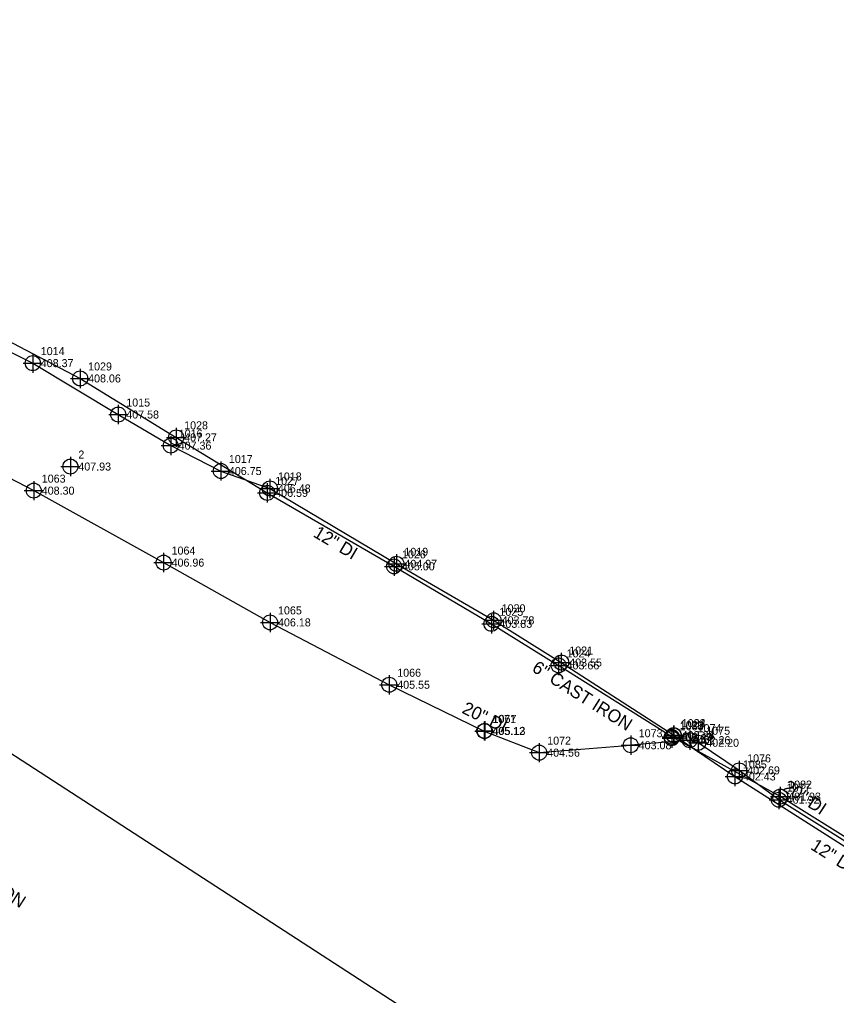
# Model space of a CAD drawing. Extents: x 2024146 to 2025516, y 819906 to 820765.
# Drawn here: x 2024389.9 to 2024645.2, y 820438.4 to 820743.2 of the extents above; entities that cross this region are included whole.
import ezdxf

# ---------------------------------------------------------------- set-up
doc = ezdxf.new("R2010")
doc.units = 0
for name, color, linetype in [('Prop Conc 4in Sidewalk', 7, 'Continuous'), ('Prop DSN Text', 7, 'Continuous'), ('Prop Lane Lines', 7, 'Continuous'), ('Sheet Block Revision CELL', 7, 'Continuous'), ('Sheet Data Field CELL', 7, 'Continuous'), ('Sheet Layout Plan Border', 7, 'Continuous'), ('Sheet Layout Profile Border Port 2', 7, 'Continuous'), ('Sheet Plan And Profile CELL', 7, 'Continuous'), ('Sheet Profile Grid Minor CELL', 7, 'Continuous')]:
    doc.layers.add(name, color=color, linetype=linetype)

msp = doc.modelspace()

# ---------------------------------------------------------------- linework, layer by layer
at = {"layer": 'Prop Lane Lines'}
msp.add_lwpolyline([(2024146.4, 820670.11), (2024566.33, 820397.9)], dxfattribs=at)
at = {"layer": 'Sheet Layout Plan Border'}
for points in [[(2024394.04, 820638.87), (2024394.04, 820635.87)], [(2024391.04, 820635.87), (2024394.04, 820635.87)], [(2024394.04, 820635.87), (2024397.04, 820635.87)], [(2024394.04, 820635.87), (2024394.04, 820632.87)], [(2024408.84, 820634.09), (2024408.84, 820631.09)], [(2024405.84, 820631.09), (2024408.84, 820631.09)], [(2024408.84, 820631.09), (2024411.84, 820631.09)], [(2024408.84, 820631.09), (2024408.84, 820628.09)], [(2024420.76, 820622.82), (2024420.76, 820619.82)], [(2024417.76, 820619.82), (2024420.76, 820619.82)], [(2024420.76, 820619.82), (2024423.76, 820619.82)], [(2024420.76, 820619.82), (2024420.76, 820616.82)], [(2024438.85, 820615.69), (2024438.85, 820612.69)], [(2024435.85, 820612.69), (2024438.85, 820612.69)], [(2024437.15, 820613.11), (2024437.15, 820610.11)], [(2024438.85, 820612.69), (2024441.85, 820612.69)], [(2024438.85, 820612.69), (2024438.85, 820609.69)], [(2024434.15, 820610.11), (2024437.15, 820610.11)], [(2024437.15, 820610.11), (2024440.15, 820610.11)], [(2024437.15, 820610.11), (2024437.15, 820607.11)], [(2024405.78, 820606.57), (2024405.78, 820603.57)], [(2024402.78, 820603.57), (2024405.78, 820603.57)], [(2024405.78, 820603.57), (2024408.78, 820603.57)], [(2024405.78, 820603.57), (2024405.78, 820600.57)], [(2024452.82, 820605.18), (2024452.82, 820602.18)], [(2024449.82, 820602.18), (2024452.82, 820602.18)], [(2024452.82, 820602.18), (2024455.82, 820602.18)], [(2024452.82, 820602.18), (2024452.82, 820599.18)], [(2024468.14, 820599.72), (2024468.14, 820596.72)], [(2024394.35, 820599.05), (2024394.35, 820596.05)], [(2024465.14, 820596.72), (2024468.14, 820596.72)], [(2024467.31, 820598.35), (2024467.31, 820595.35)], [(2024468.14, 820596.72), (2024471.14, 820596.72)], [(2024468.14, 820596.72), (2024468.14, 820593.72)], [(2024391.35, 820596.05), (2024394.35, 820596.05)], [(2024394.35, 820596.05), (2024397.35, 820596.05)], [(2024394.35, 820596.05), (2024394.35, 820593.05)], [(2024464.31, 820595.35), (2024467.31, 820595.35)], [(2024467.31, 820595.35), (2024470.31, 820595.35)], [(2024467.31, 820595.35), (2024467.31, 820592.35)], [(2024434.92, 820576.57), (2024434.92, 820573.57)], [(2024506.93, 820575.4), (2024506.93, 820572.4)], [(2024507.67, 820576.2), (2024507.67, 820573.2)], [(2024431.92, 820573.57), (2024434.92, 820573.57)], [(2024434.92, 820573.57), (2024437.92, 820573.57)], [(2024434.92, 820573.57), (2024434.92, 820570.57)], [(2024503.93, 820572.4), (2024506.93, 820572.4)], [(2024504.67, 820573.2), (2024507.67, 820573.2)], [(2024506.93, 820572.4), (2024509.93, 820572.4)], [(2024506.93, 820572.4), (2024506.93, 820569.4)], [(2024507.67, 820573.2), (2024510.67, 820573.2)], [(2024507.67, 820573.2), (2024507.67, 820570.2)], [(2024468.18, 820557.89), (2024468.18, 820554.89)], [(2024537.38, 820557.46), (2024537.38, 820554.46)], [(2024538.07, 820558.55), (2024538.07, 820555.55)], [(2024465.18, 820554.89), (2024468.18, 820554.89)], [(2024468.18, 820554.89), (2024471.18, 820554.89)], [(2024468.18, 820554.89), (2024468.18, 820551.89)], [(2024534.38, 820554.46), (2024537.38, 820554.46)], [(2024535.07, 820555.55), (2024538.07, 820555.55)], [(2024537.38, 820554.46), (2024540.38, 820554.46)], [(2024537.38, 820554.46), (2024537.38, 820551.46)], [(2024538.07, 820555.55), (2024541.07, 820555.55)], [(2024538.07, 820555.55), (2024538.07, 820552.55)], [(2024559.19, 820545.36), (2024559.19, 820542.36)], [(2024556.19, 820542.36), (2024559.19, 820542.36)], [(2024558.37, 820544.46), (2024558.37, 820541.46)], [(2024559.19, 820542.36), (2024562.19, 820542.36)], [(2024559.19, 820542.36), (2024559.19, 820539.36)], [(2024555.37, 820541.46), (2024558.37, 820541.46)], [(2024558.37, 820541.46), (2024561.37, 820541.46)], [(2024558.37, 820541.46), (2024558.37, 820538.46)], [(2024505.44, 820538.42), (2024505.44, 820535.42)], [(2024502.44, 820535.42), (2024505.44, 820535.42)], [(2024505.44, 820535.42), (2024508.44, 820535.42)], [(2024505.44, 820535.42), (2024505.44, 820532.42)], [(2024535.14, 820523.96), (2024535.14, 820520.96)], [(2024535.27, 820524.01), (2024535.27, 820521.01)], [(2024532.14, 820520.96), (2024535.14, 820520.96)], [(2024532.27, 820521.01), (2024535.27, 820521.01)], [(2024535.14, 820520.96), (2024538.14, 820520.96)], [(2024535.14, 820520.96), (2024535.14, 820517.96)], [(2024535.27, 820521.01), (2024538.27, 820521.01)], [(2024535.27, 820521.01), (2024535.27, 820518.01)], [(2024593.71, 820521.72), (2024593.71, 820518.72)], [(2024593.76, 820522.11), (2024593.76, 820519.11)], [(2024594.32, 820522.65), (2024594.32, 820519.65)], [(2024594.35, 820522.69), (2024594.35, 820519.69)], [(2024599.33, 820521.11), (2024599.33, 820518.11)], [(2024602.02, 820520.3), (2024602.02, 820517.3)], [(2024580.9, 820519.52), (2024580.9, 820516.52)], [(2024590.71, 820518.72), (2024593.71, 820518.72)], [(2024590.76, 820519.11), (2024593.76, 820519.11)], [(2024591.32, 820519.65), (2024594.32, 820519.65)], [(2024591.35, 820519.69), (2024594.35, 820519.69)], [(2024593.71, 820518.72), (2024596.71, 820518.72)], [(2024593.71, 820518.72), (2024593.71, 820515.72)], [(2024593.76, 820519.11), (2024596.76, 820519.11)], [(2024593.76, 820519.11), (2024593.76, 820516.11)], [(2024594.32, 820519.65), (2024597.32, 820519.65)], [(2024594.32, 820519.65), (2024594.32, 820516.65)], [(2024594.35, 820519.69), (2024597.35, 820519.69)], [(2024594.35, 820519.69), (2024594.35, 820516.69)], [(2024596.33, 820518.11), (2024599.33, 820518.11)], [(2024599.02, 820517.3), (2024602.02, 820517.3)], [(2024599.33, 820518.11), (2024602.33, 820518.11)], [(2024599.33, 820518.11), (2024599.33, 820515.11)], [(2024602.02, 820517.3), (2024605.02, 820517.3)], [(2024602.02, 820517.3), (2024602.02, 820514.3)], [(2024549.3, 820514.21), (2024552.3, 820514.21)], [(2024552.3, 820517.21), (2024552.3, 820514.21)], [(2024552.3, 820514.21), (2024555.3, 820514.21)], [(2024552.3, 820514.21), (2024552.3, 820511.21)], [(2024577.9, 820516.52), (2024580.9, 820516.52)], [(2024580.9, 820516.52), (2024583.9, 820516.52)], [(2024580.9, 820516.52), (2024580.9, 820513.52)], [(2024614.79, 820511.68), (2024614.79, 820508.68)], [(2024611.79, 820508.68), (2024614.79, 820508.68)], [(2024613.47, 820509.78), (2024613.47, 820506.78)], [(2024614.79, 820508.68), (2024617.79, 820508.68)], [(2024614.79, 820508.68), (2024614.79, 820505.68)], [(2024610.47, 820506.78), (2024613.47, 820506.78)], [(2024613.47, 820506.78), (2024616.47, 820506.78)], [(2024613.47, 820506.78), (2024613.47, 820503.78)], [(2024627.17, 820502.52), (2024627.17, 820499.52)], [(2024627.61, 820503.49), (2024627.61, 820500.49)], [(2024624.17, 820499.52), (2024627.17, 820499.52)], [(2024624.61, 820500.49), (2024627.61, 820500.49)], [(2024627.17, 820499.52), (2024630.17, 820499.52)], [(2024627.17, 820499.52), (2024627.17, 820496.52)], [(2024627.61, 820500.49), (2024630.61, 820500.49)], [(2024627.61, 820500.49), (2024627.61, 820497.49)]]:
    msp.add_lwpolyline(points, dxfattribs=at)
for centre in [(2024394.04, 820635.87), (2024408.84, 820631.09), (2024420.76, 820619.82), (2024438.85, 820612.69), (2024437.15, 820610.11), (2024405.78, 820603.57), (2024452.82, 820602.18), (2024394.35, 820596.05), (2024467.31, 820595.35), (2024468.14, 820596.72), (2024434.92, 820573.57), (2024507.67, 820573.2), (2024506.93, 820572.4), (2024468.18, 820554.89), (2024538.07, 820555.55), (2024537.38, 820554.46), (2024559.19, 820542.36), (2024558.37, 820541.46), (2024505.44, 820535.42), (2024535.27, 820521.01), (2024535.14, 820520.96), (2024593.71, 820518.72), (2024593.76, 820519.11), (2024594.32, 820519.65), (2024594.35, 820519.69), (2024599.33, 820518.11), (2024580.9, 820516.52), (2024602.02, 820517.3), (2024552.3, 820514.21), (2024613.47, 820506.78), (2024614.79, 820508.68), (2024627.61, 820500.49), (2024627.17, 820499.52)]:
    msp.add_circle(centre, 2.34, dxfattribs=at)
at = {"layer": 'Sheet Plan And Profile CELL'}
for points in [[(2024210.98, 820743.19), (2024217.84, 820738.78), (2024244.24, 820722.31), (2024274.15, 820703.11), (2024311.17, 820681.15), (2024338.73, 820664.66), (2024357.44, 820654.15), (2024394.04, 820635.87), (2024420.76, 820619.83), (2024437.14, 820610.11), (2024452.82, 820602.18), (2024468.13, 820596.73), (2024507.66, 820573.2), (2024538.06, 820555.55), (2024559.18, 820542.37)], [(2024191.85, 820713.95), (2024208.67, 820704.14), (2024239.83, 820686.43), (2024256.4, 820676.24), (2024257.02, 820675.83), (2024287.67, 820658.15), (2024296.47, 820653.07), (2024329.77, 820633.23), (2024370.42, 820608.44), (2024394.34, 820596.06), (2024434.92, 820573.58), (2024468.18, 820554.9), (2024505.43, 820535.43), (2024535.14, 820520.96), (2024552.3, 820514.21)], [(2024559.18, 820542.37), (2024594.35, 820519.69), (2024613.47, 820506.78), (2024651.26, 820482.68)], [(2024698.94, 820453.07), (2024674.33, 820469.18), (2024651.95, 820483.99), (2024627.17, 820499.52), (2024614.79, 820508.68), (2024602.02, 820517.3), (2024599.33, 820518.11), (2024580.9, 820516.52)], [(2024552.3, 820514.21), (2024580.9, 820516.52), (2024581.27, 820516.52)]]:
    msp.add_lwpolyline(points, dxfattribs=at)
at = {"layer": 'Sheet Profile Grid Minor CELL'}
for points in [[(2024310.64, 820680.27), (2024313.64, 820678.67), (2024339.38, 820665.59), (2024349.09, 820660.35), (2024374.95, 820648.82), (2024408.83, 820631.1), (2024438.84, 820612.69), (2024467.31, 820595.36), (2024506.92, 820572.41), (2024537.38, 820554.46), (2024558.37, 820541.47)], [(2024627.61, 820500.49), (2024593.76, 820519.11), (2024558.37, 820541.47)], [(2024699.98, 820453.54), (2024675.04, 820469.96), (2024652.27, 820485.09), (2024627.61, 820500.49)]]:
    msp.add_lwpolyline(points, dxfattribs=at)

# ---------------------------------------------------------------- texts
at = {"layer": 'Prop Conc 4in Sidewalk'}
msp.add_text('6" CAST IRON', height=4, rotation=327.7187, dxfattribs=at).set_placement((2024549.76, 820539.81))
at = {"layer": 'Prop DSN Text'}
msp.add_text('24" PIPE NOT INCLUDED IN INVESTIGATION', height=4, rotation=327.0479, dxfattribs=at).set_placement((2024295.56, 820526.85))
at = {"layer": 'Sheet Block Revision CELL'}
for s, p in [('1014', (2024396.54, 820638.37)), ('1029', (2024411.34, 820633.59)), ('1015', (2024423.26, 820622.32)), ('1016', (2024439.65, 820612.61)), ('1028', (2024441.35, 820615.19)), ('2', (2024408.28, 820606.07)), ('1017', (2024455.32, 820604.68)), ('1063', (2024396.85, 820598.55)), ('1027', (2024469.81, 820597.85)), ('1018', (2024470.64, 820599.22)), ('1064', (2024437.42, 820576.07)), ('1019', (2024510.17, 820575.7)), ('1026', (2024509.43, 820574.9)), ('1065', (2024470.68, 820557.39)), ('1020', (2024540.57, 820558.05)), ('1025', (2024539.88, 820556.96)), ('1024', (2024560.87, 820543.96)), ('1021', (2024561.69, 820544.86)), ('1066', (2024507.94, 820537.92)), ('1071', (2024537.64, 820523.46)), ('1067', (2024537.77, 820523.51)), ('1083', (2024596.21, 820521.22)), ('1023', (2024596.26, 820521.61)), ('1022', (2024596.82, 820522.16)), ('1084', (2024596.85, 820522.19)), ('1073', (2024583.4, 820519.02)), ('1074', (2024601.83, 820520.61)), ('1075', (2024604.52, 820519.8)), ('1072', (2024554.8, 820516.71)), ('1085', (2024615.97, 820509.28)), ('1076', (2024617.29, 820511.18)), ('1082', (2024630.11, 820502.99)), ('1077', (2024629.67, 820502.02))]:
    msp.add_text(s, height=2.5, dxfattribs=at).set_placement(p)
at = {"layer": 'Sheet Data Field CELL'}
for s, rotation, p in [('12" DI', 329.2487, (2024481.39, 820581.85)), ('20" DI', 334.0336, (2024527.87, 820526.73)), ('20" DI', 326.8369, (2024628.09, 820502.61)), ('12" DI', 327.9136, (2024636.82, 820484.23))]:
    msp.add_text(s, height=4, rotation=rotation, dxfattribs=at).set_placement(p)
at = {"layer": 'Sheet Layout Profile Border Port 2'}
for s, p in [('408.37', (2024396.54, 820634.62)), ('408.06', (2024411.34, 820629.84)), ('407.58', (2024423.26, 820618.57)), ('407.27', (2024441.35, 820611.44)), ('407.36', (2024439.65, 820608.86)), ('407.93', (2024408.28, 820602.32)), ('406.75', (2024455.32, 820600.93)), ('408.30', (2024396.85, 820594.8)), ('406.59', (2024469.81, 820594.1)), ('406.48', (2024470.64, 820595.47)), ('406.96', (2024437.42, 820572.32)), ('405.00', (2024509.43, 820571.15)), ('404.97', (2024510.17, 820571.95)), ('406.18', (2024470.68, 820553.64)), ('403.83', (2024539.88, 820553.21)), ('403.78', (2024540.57, 820554.3)), ('403.66', (2024560.87, 820540.21)), ('403.55', (2024561.69, 820541.11)), ('405.55', (2024507.94, 820534.17)), ('405.12', (2024537.64, 820519.71)), ('405.13', (2024537.77, 820519.76)), ('402.49', (2024596.26, 820517.86)), ('402.24', (2024596.82, 820518.41)), ('402.28', (2024596.85, 820518.44)), ('403.08', (2024583.4, 820515.27)), ('402.24', (2024596.21, 820517.47)), ('402.26', (2024601.83, 820516.86)), ('402.20', (2024604.52, 820516.05)), ('404.56', (2024554.8, 820512.96)), ('402.69', (2024617.29, 820507.43)), ('402.43', (2024615.97, 820505.53)), ('401.92', (2024629.67, 820498.27)), ('401.93', (2024630.11, 820499.24))]:
    msp.add_text(s, height=2.5, dxfattribs=at).set_placement(p)

doc.saveas('drawing.dxf')
